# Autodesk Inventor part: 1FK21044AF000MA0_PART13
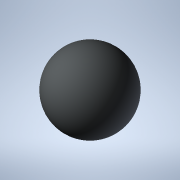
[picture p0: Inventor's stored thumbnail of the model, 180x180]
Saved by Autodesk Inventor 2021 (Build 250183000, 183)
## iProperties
Created: 2025-04
Part Number: 1FK21044AF000MA0_PART13
Material: Generic
Catalog Web Link: www.3dfindit.com
Description: -Servo synchronous motor
Document SubType Name: Modeling
Designer: psAdmin
Mass: 0.137258 g
Surface Area: 1.2868 cm^2
Volume: 0.137258 cm^3
Density: 1 g/cm^3
Appearance: PSOLRGB-212-217-219
Category: PARTsolutions
Title: 1FK21044AF000MA0_PART13
Author: Cadenas PARTsolutions
Comments: Servo synchronous motor
Sending System: PARTsolutions
Preprocessor: ST-DEVELOPER v19.3
PSOL_IDENT_0: {$CADENAS_DATA/23d-libs/siemens_ag/_cat_/39/c4/1fk21044af000ma0.prj},216 {VTYP=3D},{NB=1FK21044AF000
PSOL_IDENT_1: MA0_PART13},{LINA=1FK21044AF000MA0_PART13},{NN=1FK21044AF000MA0_PART13},{NOPRJ=TRUE},{DATE=19.08.202
PSOL_IDENT_2: 5 14:00:33},{GEOMDATE=30.07.2025 02:02:22},{VERSION=},{LINEID=10},{WBVAR=},{WBNUMERIC=}  {NB=1FK2104
PSOL_IDENT_3: 4AF000MA0_PART13},{LINA=1FK21044AF000MA0_PART13},{KT=DUMMY},{PREVIEW=../../../_pool_/cb/72/p_d211_xx
PSOL_IDENT_4: _00434j.png},{DESCSHORT=SIMOTICS S-1FK2 HD, SINAMICS S210 3AC 400V-480V, 1.27 Nm, 3000 rpm},{DESCLON
PSOL_IDENT_5: G=SIMOTICS S-1FK2 HD servo motor M0=1.27 Nm; PN = 0.4 kW at nN=3000 rpm (380-480 V); PN = 0.2 kW at
PSOL_IDENT_6: nN=1500 rpm (200-240 V); degree of protection IP64; cylindrical shaft D19x40mm; absolute encoder 22-
PSOL_IDENT_7: bit + 12-bit multiturn (encoder AM22DQC); with OCC interface; plug size M17, rotatable; SIMOTICS S-1
PSOL_IDENT_8: FK2 servomotorfor a wide range of uses in industrial environments. SIMOTICS S‑1FK2 servomotors are c
PSOL_IDENT_9: ompact synchronous motors with a high dynamic performance that set themselves apart as a result of t
PSOL_IDENT_10: heir high power density, degree of protection and overload capability. The motors are available in t
PSOL_IDENT_11: wo variants: as High Dynamic variant (highest dynamic performance as a result of the low intrinsic m
PSOL_IDENT_12: oment of inertia for applications demanding a high dynamic performance with low moved masses) - and
PSOL_IDENT_13: as Compact variant (precise and stable closed-loop control for medium up to large moved masses as a
PSOL_IDENT_14: result of a medium intrinsic moment of inertia). SIMOTICSS‑1FK2 servomotors fully exploit their stre
PSOL_IDENT_15: ngths in a system with the SINAMICSS210 frequency converter and simple connection using the one cabl
PSOL_IDENT_16: e connection (OCC). Advantages include the short control and positioning times, fast and precise cor
PSOL_IDENT_17: rection of disturbing quantities as well as stable control with a high dynamic performance. The serv
PSOL_IDENT_18: o motors can be configured to address a wide range of requirements. For example with and without hol
PSOL_IDENT_19: ding brake, IP64 or IP65 degree of protection, singleturn or multiturn absolute encoders - to name j
PSOL_IDENT_20: ust a few. Further, the servomotors are available in different shaft heights extending from 20 to 10
PSOL_IDENT_21: 0. A shaft sealing ring is available to achieve an IP65 degree of protection and for subsequent moun
PSOL_IDENT_22: ting at the motor or as spare part. SIMOTICS - the optimum motor for each and every motion control a
PSOL_IDENT_23: pplication.},{INTNO=804766906428},{SUPPLIERALTNO=1FK2104-4AF00-0MA0},{MANUID=1FK21044AF000MA0},{MANU
PSOL_IDENT_24: NAME=Siemens},{MANUTYPEDESC=Synchronous motor 1FK2-HD 1.27 NM},{AAU732=SIMOTICS},{AAO057=S-1FK2},{AA
PSOL_IDENT_25: U734=SIMOTICS S-1FK2 HD servo motor M0=1.27 Nm; PN = 0.4 kW at nN=3000 rpm (380-480 V); PN = 0.2 kW
PSOL_IDENT_26: at nN=1500 rpm (200-240 V); degree of protection IP64; cylindrical shaft D19x40mm; absolute encoder
PSOL_IDENT_27: 22-bit + 12-bit multiturn (encoder AM22DQC); with OCC interface; plug size M17, rotatable;},{AAW338=
PSOL_IDENT_28: Synchronous motor 1FK2-HD 1.27 NM},{AAO742=SIMOTICS},{AAO663=4042948693322},{NOCUPEROU=1},{PRICEQUAN
PSOL_IDENT_29: TITY=1},{QUANTITYMIN=1},{QUANTITYINT=1},{CTN=85015100},{COO=DE},{AAO676=1FK2104-4AF00-0MA0},{AAO677=
PSOL_IDENT_30: Siemens AG},{ORDERUNIT=C62},{CONTENTUNIT=C62}
NB: 1FK21044AF000MA0_PART13
NT: Servo synchronous motor
NBSYN: $MANUID._PART13
LINA: 1FK21044AF000MA0_PART13
CATALOG: SIEMENS
PREVIEW: ../../../_pool_/cb/72/p_d211_xx_00434j.png
DESCSHORT: SIMOTICS S-1FK2 HD, SINAMICS S210 3AC 400V-480V, 1.27 Nm, 3000 rpm
DESCLONG: SIMOTICS S-1FK2 HD servo motor M0=1.27 Nm; PN = 0.4 kW at nN=3000 rpm (380-480 V); PN = 0.2 kW at nN=1500 rpm (200-240 V); degree of protection IP64; cylindrica
INTNO: 804766906428
SUPPLIERALTNO: 1FK2104-4AF00-0MA0
MANUID: 1FK21044AF000MA0
MANUNAME: Siemens
MANUTYPEDESC: Synchronous motor 1FK2-HD 1.27 NM
AAU732: SIMOTICS
AAO057: S-1FK2
AAU734: SIMOTICS S-1FK2 HD servo motor M0=1.27 Nm; PN = 0.4 kW at nN=3000 rpm (380-480 V); PN = 0.2 kW at nN=1500 rpm (200-240 V); degree of protection IP64; cylindrica
AAW338: Synchronous motor 1FK2-HD 1.27 NM
AAO742: SIMOTICS
AAO663: 4042948693322.0
NOCUPEROU: 1
PRICEQUANTITY: 1
QUANTITYMIN: 1
QUANTITYINT: 1
CTN: 85015100
COO: DE
ARTICLENO: 1FK21044AF000MA0_PART13
BOMINFO: 1FK21044AF000MA0_PART13
CREATOR: CADENAS GmbH
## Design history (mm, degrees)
feature "2025_04_17_15_01_28_0038"
body "Solid1"
